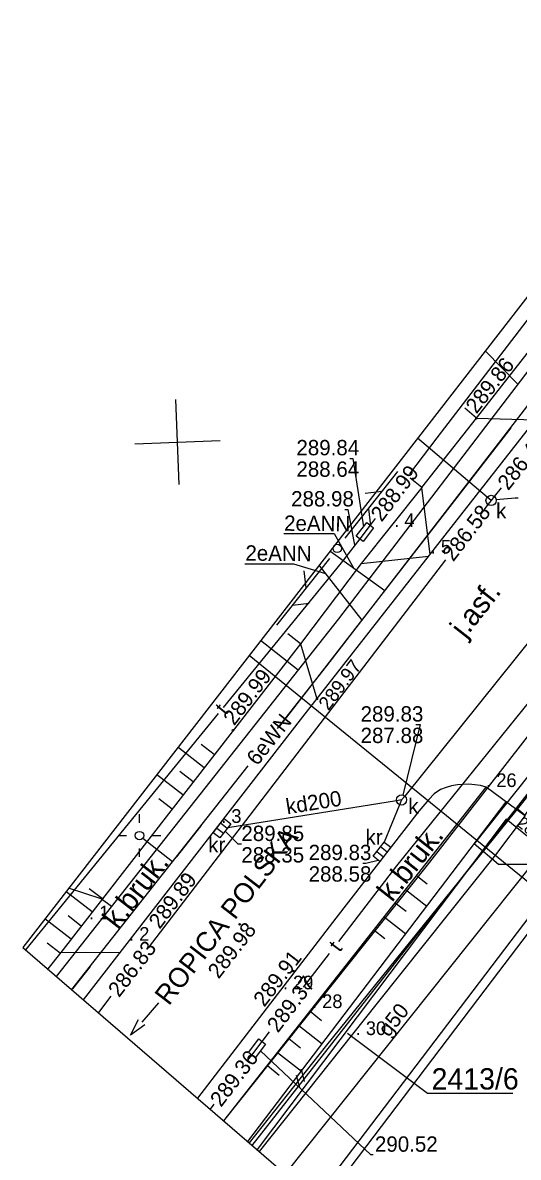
# Model space of a CAD drawing. Extents: x 4632591 to 4651936, y 5351032 to 5369988.
# Drawn here: x 4642042.8 to 4642071.8, y 5358377 to 5358443.5 of the extents above; entities that cross this region are included whole.
import ezdxf

# ---------------------------------------------------------------- set-up
doc = ezdxf.new("R2010")
doc.units = 0
for name, color, linetype in [('EBTOO_992', 7, 'Continuous'), ('EDZPD_211', 7, 'Continuous'), ('EDZPD_219', 7, 'Continuous'), ('EDZPX_299', 7, 'Continuous'), ('SDRPK_422', 7, 'Continuous'), ('SDRPK_423', 7, 'Continuous'), ('SDRPK_432', 7, 'Continuous'), ('SZOPO_902', 7, 'Continuous'), ('UEEPA_510', 7, 'Continuous'), ('UEEPB_665', 7, 'Continuous'), ('UEEPO_585', 7, 'Continuous'), ('UEETA_515', 7, 'Continuous'), ('UGGPO_583', 7, 'Continuous'), ('UKKPA_506', 7, 'Continuous'), ('UKKPA_509', 7, 'Continuous'), ('UKKPO_582', 7, 'Continuous'), ('UTTPA_504', 7, 'Continuous'), ('UTTPA_510', 7, 'Continuous'), ('UTTPO_586', 7, 'Continuous'), ('UTTTA_521', 7, 'Continuous'), ('UWWPO_581', 7, 'Continuous'), ('Warstwa 40', 7, 'Continuous'), ('Warstwa 50', 7, 'Continuous'), ('Warstwa 62', 7, 'Continuous'), ('WUKPS_403', 7, 'Continuous'), ('WUKPS_820', 7, 'Continuous'), ('WUKPS_824', 7, 'Continuous')]:
    doc.layers.add(name, color=color, linetype=linetype)

msp = doc.modelspace()

# ---------------------------------------------------------------- linework, layer by layer
at = {"layer": 'EBTOO_992'}
for p, q in [((4642050.74, 5358386.079), (4642049.76, 5358384.943)), ((4642049.107, 5358384.186), (4642049.571, 5358385.106)), ((4642049.95, 5358384.78), (4642049.107, 5358384.186))]:
    msp.add_line(p, q, dxfattribs=at)
at = {"layer": 'EDZPD_211'}
msp.add_lwpolyline([(4642071.526, 5358380.77), (4642066.529, 5358380.77), (4642061.826, 5358384.281)], dxfattribs=at)
at = {"layer": 'EDZPD_219'}
for p, q in [((4642071.737, 5358397.497), (4642074.351, 5358400.837)), ((4642056.245, 5358377.72), (4642071.737, 5358397.497)), ((4642072.251, 5358397.064), (4642071.737, 5358397.497))]:
    msp.add_line(p, q, dxfattribs=at)
msp.add_lwpolyline([(4642072.251, 5358397.064), (4642070.5, 5358394.75), (4642063.578, 5358386.058), (4642056.656, 5358377.366)], dxfattribs=at)
at = {"layer": 'EDZPX_299'}
for p, q in [((4642058.826, 5358381.842), (4642059.016, 5358381.116)), ((4642059.106, 5358382.194), (4642059.296, 5358381.468))]:
    msp.add_line(p, q, dxfattribs=at)
at = {"layer": 'SDRPK_422'}
for points in [[(4642046.346, 5358386.256), (4642059.209, 5358402.838), (4642079.221, 5358428.387), (4642102.017, 5358457.701), (4642106.446, 5358463.396)], [(4642074.26, 5358399.915), (4642072.2, 5358397.07), (4642069.96, 5358398.73)], [(4642067.285, 5358398.593), (4642066.92, 5358398.332), (4642066.598, 5358397.995), (4642066.019, 5358397.308), (4642061.146, 5358391.051), (4642053.025, 5358380.497)]]:
    msp.add_lwpolyline(points, dxfattribs=at)
msp.add_arc((4642068.82, 5358394.806), 4.086, 73.80192, 112.07072, dxfattribs=at)
at = {"layer": 'SDRPK_423'}
for p, q in [((4642069.391, 5358420.35), (4642068.715, 5358420.935)), ((4642066.182, 5358416.292), (4642065.497, 5358416.837)), ((4642066.182, 5358416.292), (4642062.622, 5358411.832)), ((4642062.622, 5358411.832), (4642059.066, 5358407.132)), ((4642062.622, 5358411.832), (4642066.589, 5358412.26)), ((4642059.066, 5358407.132), (4642058.338, 5358407.72)), ((4642059.066, 5358407.132), (4642060.034, 5358403.892)), ((4642054.581, 5358379.155), (4642069.96, 5358398.73)), ((4642045.018, 5358389.039), (4642048.517, 5358389.055))]:
    msp.add_line(p, q, dxfattribs=at)
for points in [[(4642069.391, 5358420.35), (4642082.068, 5358436.521), (4642089.705, 5358446.472), (4642096.05, 5358454.573)], [(4642066.668, 5358412.36), (4642066.182, 5358416.292), (4642069.391, 5358420.35), (4642072.86, 5358420.266)], [(4642059.066, 5358407.132), (4642045.018, 5358389.039), (4642044.25, 5358388.063)]]:
    msp.add_lwpolyline(points, dxfattribs=at)
at = {"layer": 'SZOPO_902'}
msp.add_lwpolyline([(4642093.675, 5358375.238), (4642093.82, 5358378.42), (4642071.13, 5358396.843), (4642056.53, 5358377.475)], dxfattribs=at)
at = {"layer": 'UEEPA_510'}
msp.add_circle((4642049.627, 5358395.882), 0.25, dxfattribs=at)
at = {"layer": 'UEEPB_665'}
for p, q in [((4642071.407, 5358419.794), (4642057.779, 5358402.228)), ((4642053.228, 5358396.456), (4642051.777, 5358394.616)), ((4642046.728, 5358388.211), (4642045.698, 5358386.905))]:
    msp.add_line(p, q, dxfattribs=at)
at = {"layer": 'UEEPO_585'}
for p, q in [((4642064.019, 5358410.231), (4642060.794, 5358412.559)), ((4642062.685, 5358408.506), (4642060.161, 5358411.743)), ((4642049.824, 5358395.728), (4642051.572, 5358394.355))]:
    msp.add_line(p, q, dxfattribs=at)
for points in [[(4642054.575, 5358379.16), (4642066.53, 5358394.148), (4642076.799, 5358407.337), (4642101.078, 5358438.902), (4642111.05, 5358451.701), (4642113.718, 5358455.085)], [(4642057.726, 5358402.161), (4642060.615, 5358405.826), (4642078.174, 5358428.552), (4642089.988, 5358443.709)], [(4642058.094, 5358413.598), (4642061.042, 5358413.598), (4642062.196, 5358411.547)], [(4642055.799, 5358411.812), (4642058.666, 5358411.812), (4642060.545, 5358411.25)], [(4642045.656, 5358386.851), (4642055.996, 5358399.967)]]:
    msp.add_lwpolyline(points, dxfattribs=at)
at = {"layer": 'UEETA_515'}
for p, q in [((4642049.627, 5358396.632), (4642049.627, 5358397.132)), ((4642048.377, 5358395.882), (4642048.877, 5358395.882)), ((4642050.377, 5358395.882), (4642050.877, 5358395.882)), ((4642049.627, 5358394.632), (4642049.627, 5358395.132))]:
    msp.add_line(p, q, dxfattribs=at)
at = {"layer": 'UGGPO_583'}
for p, q in [((4642071.838, 5358422.336), (4642069.899, 5358424.299)), ((4642058.937, 5358405.575), (4642056.729, 5358407.318))]:
    msp.add_line(p, q, dxfattribs=at)
for points in [[(4642116.682, 5358455.22), (4642109.134, 5358445.43), (4642104.05, 5358438.836), (4642089.709, 5358420.234), (4642080.639, 5358408.784), (4642072.095, 5358397.815), (4642060.525, 5358383.492), (4642056.06, 5358377.88)], [(4642117.035, 5358454.938), (4642102.445, 5358436.723), (4642096.695, 5358429.318), (4642094.232, 5358426.145), (4642093.25, 5358423.032), (4642091.283, 5358420.672), (4642088.305, 5358419.013), (4642086.886, 5358418.223), (4642082.568, 5358412.471), (4642075.744, 5358403.542), (4642069.267, 5358395.407)], [(4642044.753, 5358387.63), (4642061.316, 5358408.584), (4642073.313, 5358424.264)], [(4642072.636, 5358394.185), (4642070.68, 5358394.185), (4642069.267, 5358395.407)], [(4642084.494, 5358384.567), (4642072.636, 5358394.185), (4642058.171, 5358376.059)], [(4642047.994, 5358391.731), (4642047.376, 5358392.181), (4642045.469, 5358392.8)]]:
    msp.add_lwpolyline(points, dxfattribs=at)
at = {"layer": 'UKKPA_506'}
for points in [[(4642071.833, 5358415.659), (4642071.653, 5358415.659), (4642070.547, 5358415.575)], [(4642065.832, 5358402.387), (4642066.082, 5358402.387), (4642065.072, 5358398.261)]]:
    msp.add_lwpolyline(points, dxfattribs=at)
for centre in [(4642070.25, 5358415.531), (4642064.995, 5358397.971)]:
    msp.add_circle(centre, 0.3, dxfattribs=at)
at = {"layer": 'UKKPA_509'}
for p, q in [((4642054.768, 5358396.298), (4642054.373, 5358396.604)), ((4642054.159, 5358396.328), (4642054.554, 5358396.021)), ((4642064.159, 5358394.919), (4642063.765, 5358395.227)), ((4642063.55, 5358394.951), (4642063.944, 5358394.643))]:
    msp.add_line(p, q, dxfattribs=at)
for points in [[(4642054.983, 5358396.574), (4642054.339, 5358395.745), (4642053.944, 5358396.051), (4642054.588, 5358396.881)], [(4642063.335, 5358394.674), (4642063.98, 5358395.503), (4642064.374, 5358395.196), (4642063.729, 5358394.367)]]:
    msp.add_lwpolyline(points, close=True, dxfattribs=at)
for points in [[(4642055.605, 5358395.384), (4642055.425, 5358395.384), (4642054.649, 5358396.141)], [(4642062.731, 5358394.264), (4642062.911, 5358394.264), (4642063.635, 5358394.44)]]:
    msp.add_lwpolyline(points, dxfattribs=at)
at = {"layer": 'UKKPO_582'}
for p, q in [((4642070.021, 5358415.725), (4642065.934, 5358419.186)), ((4642070.25, 5358415.531), (4642070.021, 5358415.725)), ((4642064.699, 5358397.924), (4642054.804, 5358396.343)), ((4642064.995, 5358397.971), (4642064.699, 5358397.924))]:
    msp.add_line(p, q, dxfattribs=at)
for points in [[(4642080.481, 5358417.234), (4642065.183, 5358398.204)], [(4642070.436, 5358415.766), (4642070.25, 5358415.531), (4642070.067, 5358415.293)], [(4642070.839, 5358416.271), (4642070.436, 5358415.766)], [(4642070.067, 5358415.293), (4642069.623, 5358414.713)], [(4642067.582, 5358412.053), (4642050.134, 5358389.309)], [(4642065.183, 5358398.204), (4642064.995, 5358397.971), (4642064.881, 5358397.694)], [(4642064.881, 5358397.694), (4642063.979, 5358395.504)], [(4642047.955, 5358386.47), (4642047.216, 5358385.506)]]:
    msp.add_lwpolyline(points, dxfattribs=at)
at = {"layer": 'UTTPA_504'}
for points in [[(4642061.957, 5358417.997), (4642062.137, 5358417.997), (4642062.759, 5358413.978)], [(4642063.342, 5358377.172), (4642063.206, 5358377.173), (4642056.726, 5358383.269)]]:
    msp.add_lwpolyline(points, dxfattribs=at)
for points in [[(4642062.345, 5358413.437), (4642062.953, 5358414.231), (4642063.35, 5358413.927), (4642062.742, 5358413.133)], [(4642056.018, 5358383.167), (4642056.626, 5358383.961), (4642057.023, 5358383.657), (4642056.415, 5358382.863)]]:
    msp.add_lwpolyline(points, close=True, dxfattribs=at)
at = {"layer": 'UTTPA_510'}
msp.add_circle((4642061.229, 5358412.722), 0.25, dxfattribs=at)
at = {"layer": 'UTTPO_586'}
for points in [[(4642079.943, 5358435.997), (4642067.072, 5358419.196), (4642065.458, 5358417.089)], [(4642061.313, 5358389.673), (4642064.713, 5358394.115), (4642076.623, 5358408.846), (4642080.748, 5358414.163), (4642082.068, 5358415.865)], [(4642061.664, 5358414.998), (4642061.844, 5358414.998), (4642062.231, 5358412.917)], [(4642063.446, 5358414.463), (4642063.152, 5358414.079)], [(4642063.152, 5358414.079), (4642062.544, 5358413.285)], [(4642062.544, 5358413.285), (4642061.465, 5358411.877), (4642054.537, 5358403.394)], [(4642054.249, 5358403.042), (4642051.552, 5358399.74), (4642042.938, 5358389.194)], [(4642059.258, 5358386.988), (4642060.769, 5358388.962)], [(4642056.216, 5358383.015), (4642056.824, 5358383.809)], [(4642056.824, 5358383.809), (4642057.254, 5358384.371)], [(4642055.991, 5358382.721), (4642056.216, 5358383.015)], [(4642053.786, 5358379.841), (4642054.009, 5358380.132)]]:
    msp.add_lwpolyline(points, dxfattribs=at)
at = {"layer": 'UTTTA_521'}
for p, q in [((4642061.694, 5358413.311), (4642064.79, 5358417.237)), ((4642063.861, 5358416.059), (4642062.868, 5358415.942)), ((4642063.061, 5358415.044), (4642063.178, 5358414.051)), ((4642060.764, 5358412.134), (4642057.664, 5358408.211)), ((4642059.396, 5358410.402), (4642059.28, 5358411.395)), ((4642058.594, 5358409.388), (4642059.587, 5358409.504))]:
    msp.add_line(p, q, dxfattribs=at)
at = {"layer": 'UWWPO_581'}
for points in [[(4642119.505, 5358452.965), (4642092.32, 5358417.221), (4642069.914, 5358387.761), (4642059.891, 5358374.577)], [(4642119.925, 5358452.629), (4642092.728, 5358416.87), (4642070.321, 5358387.409), (4642060.298, 5358374.225)], [(4642056.057, 5358406.452), (4642079.418, 5358387.494), (4642088.049, 5358380.335), (4642111.658, 5358359.52), (4642125.607, 5358374.517), (4642135.429, 5358384.532), (4642137.11, 5358386.245), (4642142.399, 5358380.981)]]:
    msp.add_lwpolyline(points, dxfattribs=at)
at = {"layer": 'Warstwa 40'}
for p, q in [((4642102.603, 5358466.465), (4642042.779, 5358389.332)), ((4642042.779, 5358389.332), (4642109.608, 5358331.706))]:
    msp.add_line(p, q, dxfattribs=at)
at = {"layer": 'Warstwa 50'}
for p, q in [((4642051.962, 5358416.456), (4642051.764, 5358421.452)), ((4642049.365, 5358418.855), (4642054.361, 5358419.053))]:
    msp.add_line(p, q, dxfattribs=at)
at = {"layer": 'WUKPS_403'}
for centre in [(4642069.391, 5358420.35), (4642060.034, 5358403.892), (4642055.119, 5358402.066), (4642052.137, 5358393.512), (4642055.504, 5358390.686), (4642058.652, 5358387.945)]:
    msp.add_circle(centre, 0.045, dxfattribs=at)
at = {"layer": 'WUKPS_820'}
for p, q in [((4642054.016, 5358400.628), (4642053.243, 5358401.228)), ((4642053.419, 5358399.859), (4642051.874, 5358401.059)), ((4642052.18, 5358398.263), (4642050.635, 5358399.462)), ((4642052.777, 5358399.032), (4642052.004, 5358399.631)), ((4642051.537, 5358397.435), (4642050.765, 5358398.034)), ((4642065.884, 5358393.541), (4642066.499, 5358393.058)), ((4642046.854, 5358391.404), (4642045.313, 5358392.6)), ((4642047.451, 5358392.172), (4642046.68, 5358392.771)), ((4642065.235, 5358392.716), (4642066.479, 5358391.738)), ((4642064.633, 5358391.949), (4642065.261, 5358391.456)), ((4642046.212, 5358390.576), (4642045.441, 5358391.174)), ((4642063.985, 5358391.124), (4642065.253, 5358390.127)), ((4642045.615, 5358389.807), (4642044.074, 5358391.003)), ((4642063.382, 5358390.357), (4642064.023, 5358389.854)), ((4642044.973, 5358388.981), (4642044.207, 5358389.584)), ((4642059.63, 5358385.582), (4642060.307, 5358385.05)), ((4642058.982, 5358384.756), (4642060.348, 5358383.683)), ((4642058.38, 5358383.99), (4642059.069, 5358383.448)), ((4642057.731, 5358383.164), (4642059.122, 5358382.072)), ((4642057.129, 5358382.398), (4642057.83, 5358381.847))]:
    msp.add_line(p, q, dxfattribs=at)
at = {"layer": 'WUKPS_824'}
msp.add_line((4642055.982, 5358377.947), (4642071.137, 5358397.857), dxfattribs=at)

# ---------------------------------------------------------------- texts
at = {"layer": 'EDZPD_211'}
msp.add_text('2413/6', height=1.25, dxfattribs=at).set_placement((4642066.76, 5358380.997))
at = {"layer": 'SDRPK_423'}
for rotation, p in [(51.8465, (4642064.445, 5358391.934)), (52.17404, (4642048.353, 5358390.328))]:
    msp.add_text('k.bruk.', height=1.25, rotation=rotation, dxfattribs=at).set_placement(p)
at = {"layer": 'SDRPK_432'}
for s, height, rotation, p in [('j.asf.', 1.25, 51.92857, (4642068.723, 5358407.396)), ('ROPICA POLSKA', 1.15438, 52.42052, (4642051.351, 5358385.862))]:
    msp.add_text(s, height=height, rotation=rotation, dxfattribs=at).set_placement(p)
at = {"layer": 'UEEPO_585'}
for s, rotation, p in [('2eANN', 359.446, (4642058.109, 5358413.753)), ('2eANN', 359.446, (4642055.838, 5358412.003)), ('6eWN', 51.74959, (4642056.542, 5358399.932))]:
    msp.add_text(s, height=0.9, rotation=rotation, dxfattribs=at).set_placement(p)
at = {"layer": 'UGGPO_583'}
msp.add_text('g50', height=0.9, rotation=51.40915, dxfattribs=at).set_placement((4642064.24, 5358384.024))
at = {"layer": 'UKKPA_506'}
for s, p in [('k', (4642070.544, 5358414.475)), ('289.83', (4642062.597, 5358402.568)), ('287.88', (4642062.597, 5358401.308)), ('k', (4642065.393, 5358397.157)), ('kr', (4642053.659, 5358394.893)), ('kr', (4642062.884, 5358395.343))]:
    msp.add_text(s, height=0.9, dxfattribs=at).set_placement(p)
at = {"layer": 'UKKPA_509'}
for s, p in [('289.85', (4642055.605, 5358395.564)), ('288.35', (4642055.605, 5358394.304)), ('289.83', (4642059.55, 5358394.444)), ('288.58', (4642059.55, 5358393.184))]:
    msp.add_text(s, height=0.9, dxfattribs=at).set_placement(p)
at = {"layer": 'UKKPO_582'}
for s, rotation, p in [('286.49', 51.50476, (4642071.255, 5358416.072)), ('286.58', 52.50618, (4642068.032, 5358411.9)), ('kd200', 9.08085, (4642058.294, 5358397.129)), ('286.83', 52.50622, (4642048.431, 5358386.35))]:
    msp.add_text(s, height=0.9, rotation=rotation, dxfattribs=at).set_placement(p)
at = {"layer": 'UTTPA_504'}
for s, p in [('289.84', (4642058.832, 5358418.177)), ('288.64', (4642058.832, 5358416.917)), ('290.52', (4642063.438, 5358377.35))]:
    msp.add_text(s, height=0.9, dxfattribs=at).set_placement(p)
at = {"layer": 'UTTPO_586'}
for s, rotation, p in [('288.99', 52.54185, (4642063.831, 5358414.226)), ('t', 50.75851, (4642054.679, 5358402.894)), ('t', 52.56526, (4642061.366, 5358388.996)), ('289.37', 52.56608, (4642057.749, 5358384.276)), ('289.36', 52.5671, (4642054.412, 5358379.918))]:
    msp.add_text(s, height=0.9, rotation=rotation, dxfattribs=at).set_placement(p)
msp.add_text('288.98', height=0.9, dxfattribs=at).set_placement((4642058.522, 5358415.178))
at = {"layer": 'Warstwa 62'}
for s, p in [('. 4', (4642064.57, 5358413.97)), ('. 5', (4642066.71, 5358412.42)), ('. 26', (4642069.96, 5358398.73)), ('. 3', (4642054.42, 5358396.63)), ('. 1', (4642046.67, 5358390.97)), ('. 2', (4642049.02, 5358389.72)), ('. 29', (4642058.04, 5358386.87)), ('. 28', (4642059.75, 5358385.77)), ('. 30', (4642062.31, 5358384.19))]:
    msp.add_text(s, height=0.8, dxfattribs=at).set_placement(p)
at = {"layer": 'WUKPS_403'}
for s, height, rotation, p in [('289.86', 0.9, 51.84283, (4642069.391, 5358420.563)), ('289.97', 0.8082, 52.9332, (4642060.711, 5358403.168)), ('289.99', 0.9, 52.48222, (4642055.183, 5358402.285)), ('289.32', 0.6962, 322.29613, (4642071.698, 5358396.504)), ('289.89', 0.9, 52.69291, (4642050.812, 5358390.354)), ('289.98', 0.9, 52.23253, (4642054.273, 5358387.437)), ('289.91', 0.9, 52.35125, (4642056.947, 5358385.789))]:
    msp.add_text(s, height=height, rotation=rotation, dxfattribs=at).set_placement(p)

doc.saveas('drawing.dxf')
